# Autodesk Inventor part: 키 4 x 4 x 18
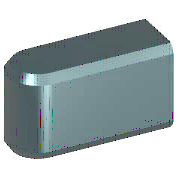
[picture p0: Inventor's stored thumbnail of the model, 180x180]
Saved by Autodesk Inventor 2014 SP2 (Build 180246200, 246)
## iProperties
IsCustomPart: 1
Created: 2012-02
Part Number: 키 4 x 4 x 18
Material: 강철, 연강
Description: 키 및 해당 키홈
Document SubType Name: Modeling
Standard: KS B 1311
Designer: mduedu
Standards Organization: KS
Language: ko-KR
Size Designation: 4 x 4 x 18
Categories: <MemberInstance><Categories><Category DisplayName="샤프트 부품" InternalName="7f7aeb1f-a693-4053-b835-cee3144e0d98" Mnemonic="SHFT"><Category DisplayName="키" Interna
Density: 1 g/cm^3
Appearance: 파란색 - 벽 페인트 - 광택
Author: mduedu
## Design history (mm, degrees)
sketch "스케치1"
  geometry: L1 (2, 2)-(18, 2); L2 (18, 2)-(18, -2); L3 (18, -2)-(2, -2); L4 (0, 7)-(0, -7) reference; L5 (-5, 0)-(30, 0) reference; A1 r 2 centre (2, 0) between (2, 2) and (2, -2)
  constraints: 6 end point, 3 tangent, 2 point on circle, 1 centre point, 1 horizontal, 1 parallel, 1 perpendicular, 1 point on line
  dimensions: "d0" = 2 radius of A1 (= 0.5 x PB); "d7" = 18 distance between parallel lines of L2 L4 (= NLG)
workplane "Work Plane1"
workplane "Work Plane2"
extrude "본체1" new body sketch "스케치1" taper "d3" = 0 deg; stored distance "d4" = 10
workaxis "Work Axis1"
workplane "Work Plane4"
body "Solid1"
chamfer "모따기1" distance "d8" = 0.25 (= PHH); stored, may be unused: second distance "d9" = 0.25 (= PHH), angle "d13" = 45 deg
other parameters: "d1" = -2.5 (= -PNT), "d2" = 1.5 (= PH - PNT), "NLG" = 18 [user parameter; used in 2 equation terms], "PB" = 4 [user parameter; used in 1 equation term], "PNT" = 2.5 [user parameter; used in 2 equation terms], "PH" = 4 [user parameter; used in 1 equation term], "PHH" = 0.25 [user parameter; used in 2 equation terms], "d10" = 0, "d16" = 0, "d17" = 0, "d18" = 0, "RR" = 0.08 [user parameter], "WDMAX" = 12 [user parameter], "PLB1" = 18 (= NLG) [user parameter], "PUEB" = 1.8 [user parameter]
